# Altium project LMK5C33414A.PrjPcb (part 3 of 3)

## Sheet LMK5C33414A_USB2ANY.SchDoc
size 431 x 279 mm; Date: Not shown in title block; ApprovedBy: Not shown in title block; CheckedBy: Not shown in title block; Author: Not shown in title block; CompanyName: Not shown in title block; Engineer: Not shown in title block; Organization: Not shown in title block; Address1: Not shown in title block; Address2: Not shown in title block; Address3: Not shown in title block; Address4: Not shown in title block; DocumentNumber: 2; Revision: Use project parameter SCH_Rev; SheetNumber: 2; SheetTotal: 3; PageSetup: Record=PageOptions¦CenterHorizontal=True¦CenterVertical=True¦PrintScale=1.00¦XCorrection=1.00¦YCorrection=1.00¦PrintKind=0¦BorderSize=5000000¦LeftOffset=0¦BottomOffset=0¦Orientation=2¦PaperLength=1000¦PaperWidth=1000¦Scale=100¦PaperSource=15¦PrintQuality=600¦MediaType=1¦DitherType=10¦PaperKind=Letter¦PrintScaleMode=1
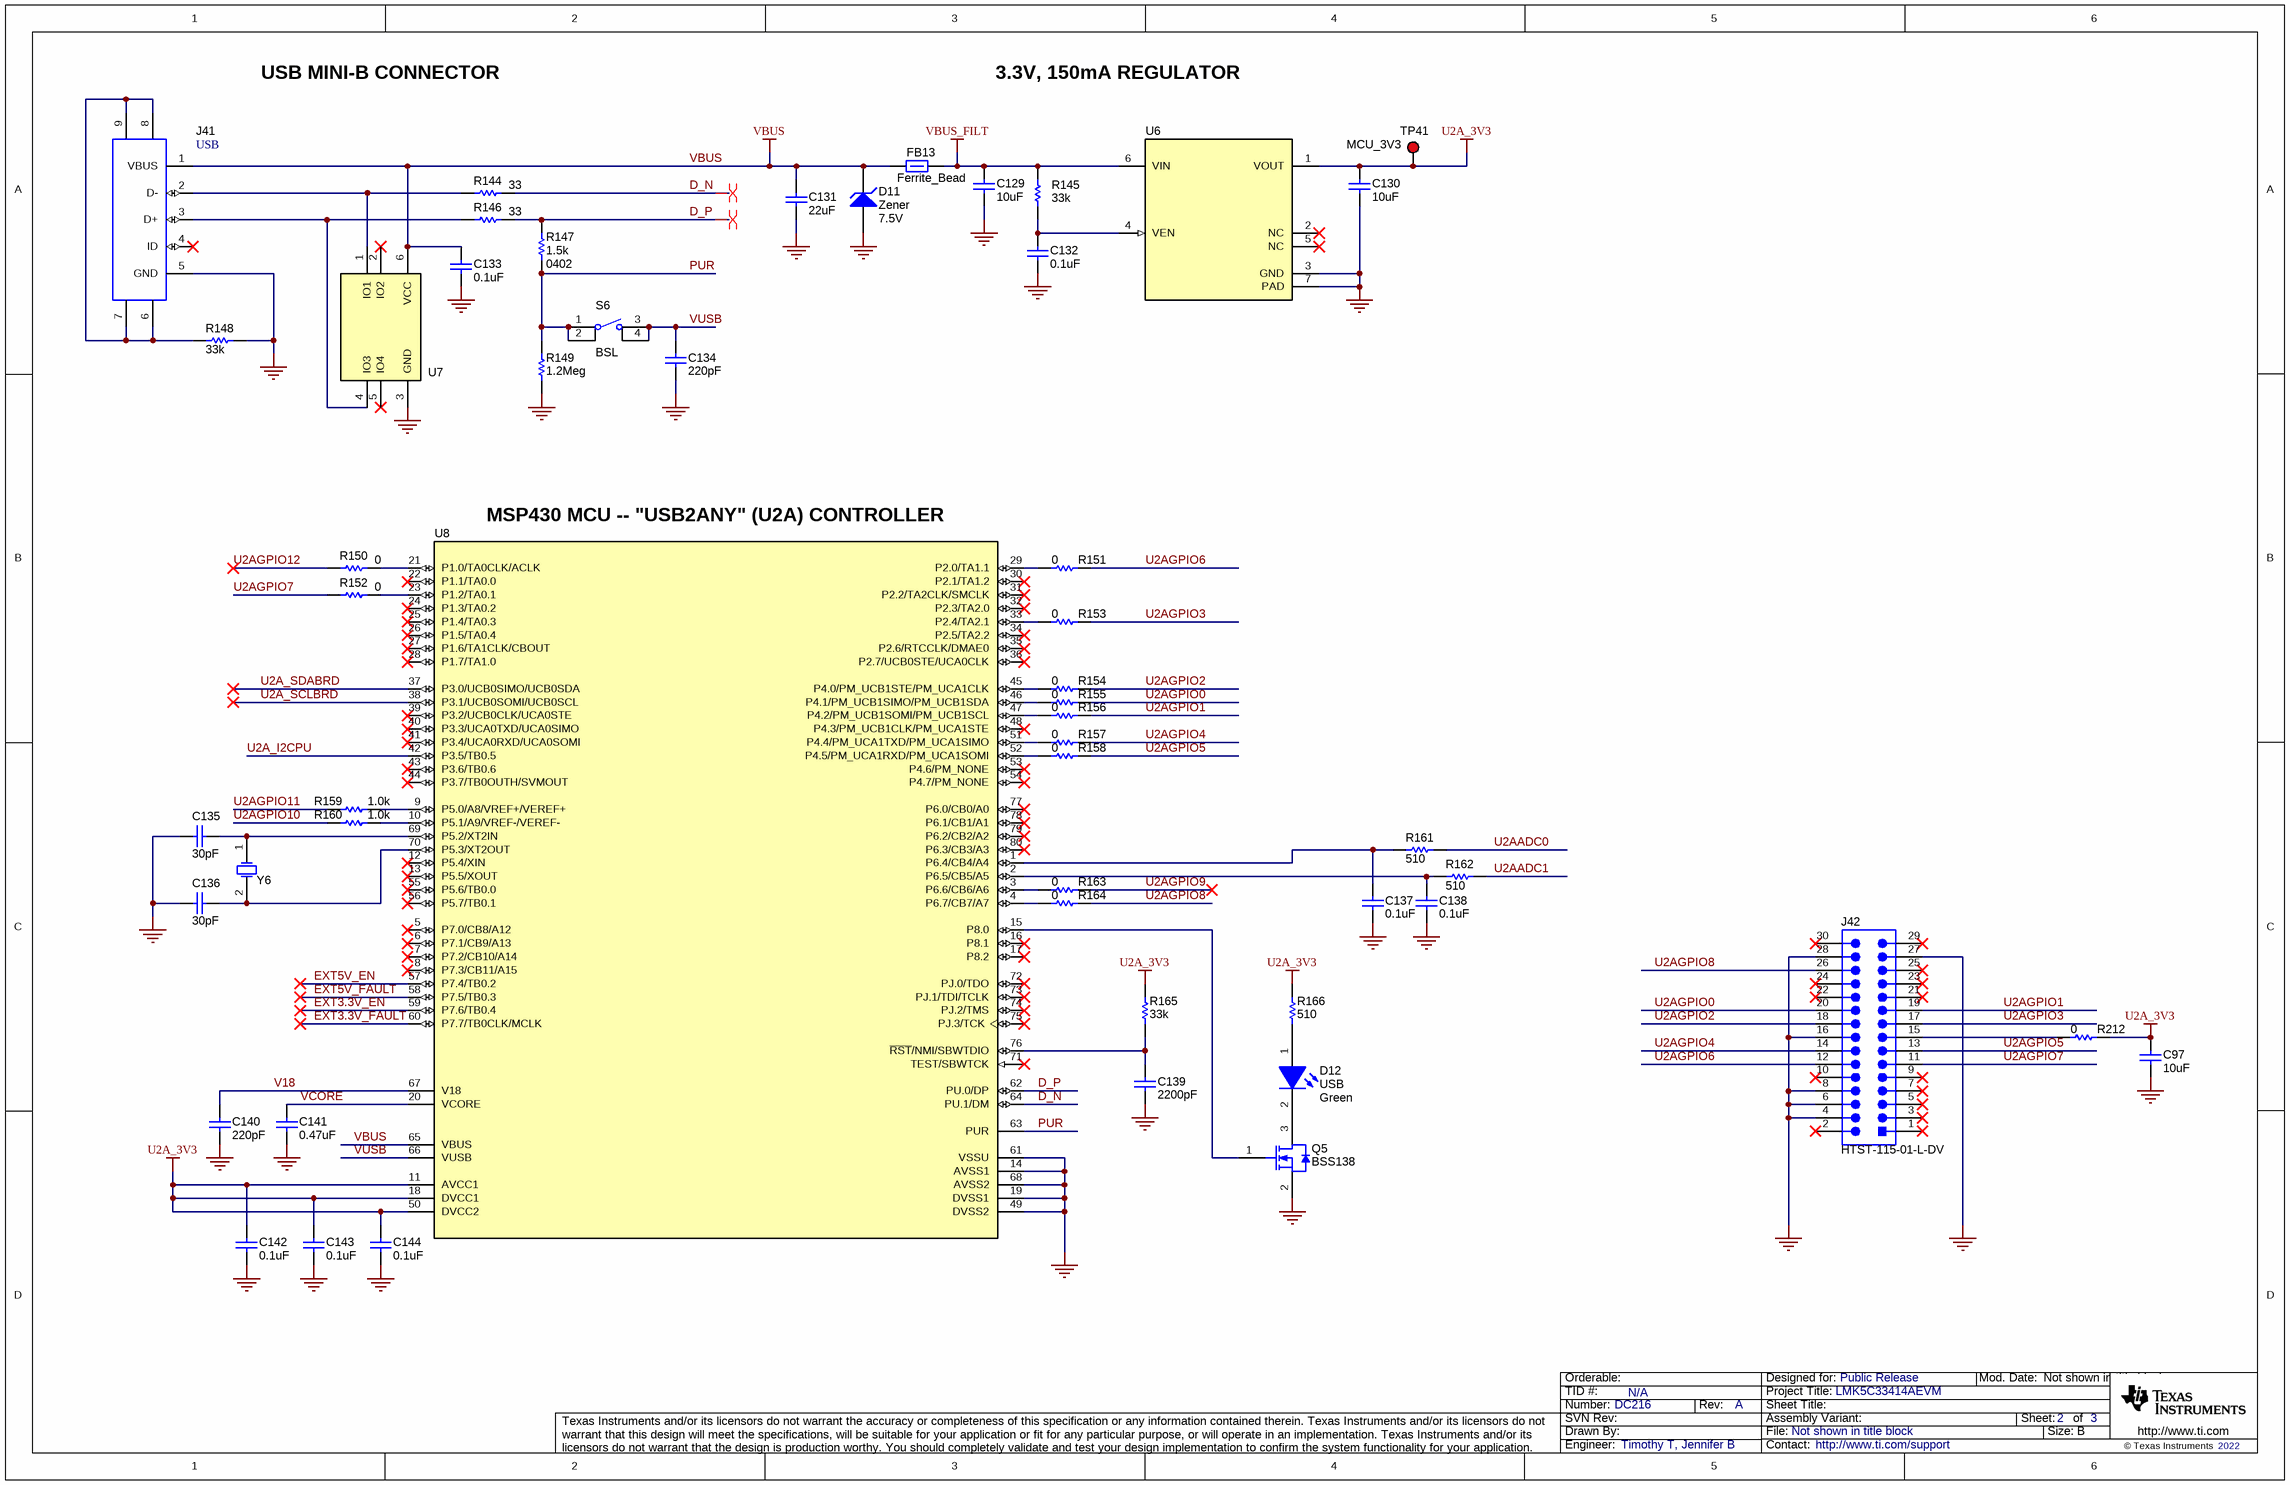
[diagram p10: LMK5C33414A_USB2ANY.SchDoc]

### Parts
C97  ValueDisplayed: 10uF  [0603]  (hidden comment: Capacitor)
C129  ValueDisplayed: 10uF  [0603]  (hidden comment: Capacitor)
C130  ValueDisplayed: 10uF  [0603]  (hidden comment: Capacitor)
C131  ValueDisplayed: 22uF  [0805]  (hidden comment: Capacitor)
C132  ValueDisplayed: 0.1uF  [0603]  (hidden comment: Capacitor)
C133  ValueDisplayed: 0.1uF  [0603]  (hidden comment: Capacitor)
C134  ValueDisplayed: 220pF  [0603]  (hidden comment: Capacitor)
C135  ValueDisplayed: 30pF  [0603]  (hidden comment: Capacitor)
C136  ValueDisplayed: 30pF  [0603]  (hidden comment: Capacitor)
C137  ValueDisplayed: 0.1uF  [0603]  (hidden comment: Capacitor)
C138  ValueDisplayed: 0.1uF  [0603]  (hidden comment: Capacitor)
C139  ValueDisplayed: 2200pF  [0603]  (hidden comment: Capacitor)
C140  ValueDisplayed: 220pF  [0603]  (hidden comment: Capacitor)
C141  ValueDisplayed: 0.47uF  [0603]  (hidden comment: Capacitor)
C142  ValueDisplayed: 0.1uF  [0603]  (hidden comment: Capacitor)
C143  ValueDisplayed: 0.1uF  [0603]  (hidden comment: Capacitor)
C144  ValueDisplayed: 0.1uF  [0603]  (hidden comment: Capacitor)
D11  Zener  value 7.5V  [SMB]
D12  USB  value Green  [LED_LTST-C190]
FB13  Ferrite_Bead  [0603]
J41  USB  [CONN_USB-Mini-B-1734035-2]
J42  HTST-115-01-L-DV  [Samtec_HTST-115-01-x-DV]
Q5  BSS138  [SOT-23]
R144  value 33  [0402]  (hidden comment: Resistor)
R145  value 33k  [0603]  (hidden comment: Resistor)
R146  value 33  [0402]  (hidden comment: Resistor)
R147  value 1.5k  [0402]  (hidden comment: Resistor)
R148  value 33k  [0603]  (hidden comment: Resistor)
R149  value 1.2Meg  [0603]  (hidden comment: Resistor)
R150  value 0  [0603]  (hidden comment: Resistor)
R151  value 0  [0603]  (hidden comment: Resistor)
R152  value 0  [0603]  (hidden comment: Resistor)
R153  value 0  [0603]  (hidden comment: Resistor)
R154  value 0  [0603]  (hidden comment: Resistor)
R155  value 0  [0603]  (hidden comment: Resistor)
R156  value 0  [0603]  (hidden comment: Resistor)
R157  value 0  [0603]  (hidden comment: Resistor)
R158  ValueDisplayed: 0  [0603]  (hidden comment: CRCW06030000Z0EA)
R159  ValueDisplayed: 1.0k  [0603]  (hidden comment: CRCW06031K00JNEA)
R160  ValueDisplayed: 1.0k  [0603]  (hidden comment: CRCW06031K00JNEA)
R161  ValueDisplayed: 510  [0603]  (hidden comment: Resistor)
R162  ValueDisplayed: 510  [0603]  (hidden comment: Resistor)
R163  value 0  [0603]  (hidden comment: Resistor)
R164  value 0  [0603]  (hidden comment: Resistor)
R165  value 33k  [0603]  (hidden comment: Resistor)
R166  ValueDisplayed: 510  [0603]  (hidden comment: Resistor)
R212  value 0  [0603]  (hidden comment: Resistor)
S6  BSL  [SW_FSM4JSMA]
TP41  MCU_3V3  [Keystone5000]
U6  LP5900SD-3.3/NOPB  [NGF0006A]  (value not drawn)
U7  TPD4E004DRYR  [DRY0006A]  (value not drawn)
U8  MSP430F5529IPN  [PN0080A_N]  (value not drawn)
Y6  Xtal  [XTAL_CSM-7X]  (value not drawn)

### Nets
GND: C97.2 C129.1 C130.2 C131.2 C132.1 C133.1 C134.1 C135.2 C136.2 C137.1 C138.1 C139.2 C140.1 C141.1 C142.1 C143.1 C144.1 D11.2(A) J41.5(GND) J42.4 J42.6 J42.8 J42.16 J42.27 J42.28 Q5.2(S) R148.2 R149.1 U6.3(GND) U6.7(PAD) U7.3(GND) U8.14(AVSS1) U8.19(DVSS1) U8.49(DVSS2) U8.61(VSSU) U8.68(AVSS2)
U2A_3V3: C97.1 C130.1 C142.2 C143.2 C144.2 R165.1 R166.2 R212.2 TP41.1 U6.1(VOUT) U8.11(AVCC1) U8.18(DVCC1) U8.50(DVCC2)
VBUS: C131.1 C133.2 D11.1(K) FB13.1 J41.1(VBUS) U7.6(VCC) U8.65(VBUS)
VBUS_FILT: C129.2 FB13.2 R145.1 U6.6(VIN)
D_N: R144.1 U8.64(PU.1/DM)
D_P: R146.1 R147.2 U8.62(PU.0/DP)
EXT3.3V_EN: U8.59(P7.6/TB0.4)
EXT3.3V_FAULT: U8.60(P7.7/TB0CLK/MCLK)
EXT5V_EN: U8.57(P7.4/TB0.2)
EXT5V_FAULT: U8.58(P7.5/TB0.3)
PUR: R147.1 R149.2 S6.1 S6.2 U8.63(PUR)
U2A_I2CPU: U8.42(P3.5/TB0.5)
U2A_SCLBRD: U8.38(P3.1/UCB0SOMI/UCB0SCL)
U2A_SDABRD: U8.37(P3.0/UCB0SIMO/UCB0SDA)
U2AADC0: R161.2
U2AADC1: R162.2
U2AGPIO0: J42.20 R155.1
U2AGPIO1: J42.19 R156.1
U2AGPIO2: J42.18 R154.2
U2AGPIO3: J42.17 R153.2
U2AGPIO4: J42.14 R157.2
U2AGPIO5: J42.13 R158.2
U2AGPIO6: J42.12 R151.2
U2AGPIO7: J42.11 R152.2
U2AGPIO8: J42.26 R164.2
U2AGPIO9: R163.2
U2AGPIO10: R160.2
U2AGPIO11: R159.2
U2AGPIO12: R150.2
V18: C140.2 U8.67(V18)
VCORE: C141.2 U8.20(VCORE)
VUSB: C134.2 S6.3 S6.4 U8.66(VUSB)
NetC132_2: C132.2 R145.2 U6.4(VEN)
NetC135_1: C135.1 U8.69(P5.2/XT2IN) Y6.1(OSC1)
NetC136_1: C136.1 U8.70(P5.3/XT2OUT) Y6.2(OSC2)
NetC137_2: C137.2 R161.1 U8.1(P6.4/CB4/A4)
NetC138_2: C138.2 R162.1 U8.2(P6.5/CB5/A5)
NetC139_1: C139.1 R165.2 U8.76(~{RST}/NMI/SBWTDIO)
NetD12_1: D12.1(A) R166.1
NetD12_2: D12.2(K) Q5.3(D)
NetJ41_2: J41.2(D-) R144.2 U7.1(IO1)
NetJ41_3: J41.3(D+) R146.2 U7.4(IO3)
NetJ41_6: J41.6 J41.7 J41.8 J41.9 R148.1
NetJ42_15: J42.15 R212.1
NetQ5_1: Q5.1(G) U8.15(P8.0)
NetR150_1: R150.1 U8.21(P1.0/TA0CLK/ACLK)
NetR151_1: R151.1 U8.29(P2.0/TA1.1)
NetR152_1: R152.1 U8.23(P1.2/TA0.1)
NetR153_1: R153.1 U8.33(P2.4/TA2.1)
NetR154_1: R154.1 U8.45(P4.0/PM_UCB1STE/PM_UCA1CLK)
NetR155_2: R155.2 U8.46(P4.1/PM_UCB1SIMO/PM_UCB1SDA)
NetR156_2: R156.2 U8.47(P4.2/PM_UCB1SOMI/PM_UCB1SCL)
NetR157_1: R157.1 U8.51(P4.4/PM_UCA1TXD/PM_UCA1SIMO)
NetR158_1: R158.1 U8.52(P4.5/PM_UCA1RXD/PM_UCA1SOMI)
NetR159_1: R159.1 U8.9(P5.0/A8/VREF+/VEREF+)
NetR160_1: R160.1 U8.10(P5.1/A9/VREF-/VEREF-)
NetR163_1: R163.1 U8.3(P6.6/CB6/A6)
NetR164_1: R164.1 U8.4(P6.7/CB7/A7)

Not connected (* = marked no-connect by the designer): J41 4(ID)*; J42 1* 2* 3* 5* 7* 9* 10* 21* 22* 23* 24* 25* 29* 30*; U6 2(NC)* 5(NC)*; U7 2(IO2)* 5(IO4)*; U8 5(P7.0/CB8/A12)* 6(P7.1/CB9/A13)* 7(P7.2/CB10/A14)* 8(P7.3/CB11/A15)* 12(P5.4/XIN)* 13(P5.5/XOUT)* 16(P8.1)* 17(P8.2)* 22(P1.1/TA0.0)* 24(P1.3/TA0.2)* 25(P1.4/TA0.3)* 26(P1.5/TA0.4)* 27(P1.6/TA1CLK/CBOUT)* 28(P1.7/TA1.0)* 30(P2.1/TA1.2)* 31(P2.2/TA2CLK/SMCLK)* 32(P2.3/TA2.0)* 34(P2.5/TA2.2)* 35(P2.6/RTCCLK/DMAE0)* 36(P2.7/UCB0STE/UCA0CLK)* 39(P3.2/UCB0CLK/UCA0STE)* 40(P3.3/UCA0TXD/UCA0SIMO)* 41(P3.4/UCA0RXD/UCA0SOMI)* 43(P3.6/TB0.6)* 44(P3.7/TB0OUTH/SVMOUT)* 48(P4.3/PM_UCB1CLK/PM_UCA1STE)* 53(P4.6/PM_NONE)* 54(P4.7/PM_NONE)* 55(P5.6/TB0.0)* 56(P5.7/TB0.1)* 71(TEST/SBWTCK)* 72(PJ.0/TDO)* 73(PJ.1/TDI/TCLK)* 74(PJ.2/TMS)* 75(PJ.3/TCK)* 77(P6.0/CB0/A0)* 78(P6.1/CB1/A1)* 79(P6.2/CB2/A2)* 80(P6.3/CB3/A3)*

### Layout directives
differential pair: D_N, D_P

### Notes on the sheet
- USB MINI-B CONNECTOR
- 3.3V, 150mA REGULATOR
- (near U8) MSP430 MCU -- "USB2ANY" (U2A) CONTROLLER

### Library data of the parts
C97 C130 = CMP-0007003-5: CAP, CERM, 10 uF, 10 V, +/- 20%, X5R, 0603; PartNumber: C1608X5R1A106M080AC; Manufacturer: TDK; Polarized: N; Value: 10uF; U/M: EA; Cap_F: 10µF; ESR_ohm: 7.8m; Value1: 0.0078 ohm; VDC_V: 10V; IRMS_A: 1.85A; TaMin_C: -55°C; TaMax_C: 85°C; SizeArea_mm2: 1.28; SizeAreaWB_mm2: 4.68; SizeX_mm: 1.6; SizeY_mm: 0.8; SizeZ_mm: 1; AEC Category: Q200
C129 = CMP-0007003-5: CAP, CERM, 10 uF, 10 V, +/- 20%, X5R, 0603; Manufacturer: TDK; PartNumber: C1608X5R1A106M080AC; ESR_ohm: 7.8m; IRMS_A: 1.85A; Polarized: N; TaMax_C: 85°C; TaMin_C: -55°C; VDC_V: 10V; Cap_F: 10µF; Value: 10uF; Value1: 0.0078 ohm; U/M: EA; SizeArea_mm2: 1.28; SizeAreaWB_mm2: 4.68; SizeX_mm: 1.6; SizeY_mm: 0.8; SizeZ_mm: 1; AEC Category: Q200
C131 = CMP-0008403-2: CAP, CERM, 22 uF, 10 V, +/- 20%, X5R, 0805; PartNumber: LMK212BJ226MG-T; Manufacturer: Taiyo Yuden; Polarized: N; Value: 22uF; U/M: EA; Cap_F: 22µF; Value1: Unknown; VDC_V: 10V; TaMin_C: -55°C; TaMax_C: 85°C; AEC Category: Q200; SizeArea_mm2: 2.5; SizeAreaWB_mm2: 6.75; SizeX_mm: 2; SizeY_mm: 1.25; SizeZ_mm: 1.45
C132 C133 C137 C138 C142-C144 = CMP-0006857-4: CAP, CERM, 0.1 uF, 16 V, +/- 5%, X7R, 0603; PartNumber: C0603C104J4RACTU; Manufacturer: Kemet; Polarized: N; Value: 0.1uF; U/M: EA; Cap_F: 100nF; Value1: Unknown; VDC_V: 16V; TaMin_C: -55°C; TaMax_C: 125°C; AEC Category: Q200; SizeArea_mm2: 1.28; SizeAreaWB_mm2: 4.68; SizeX_mm: 1.6; SizeY_mm: 0.8; SizeZ_mm: 1
C134 C140 = CMP-0006776-4: CAP, CERM, 220 pF, 50 V, +/- 1%, C0G/NP0, 0603; PartNumber: 06035A221FAT2A; Manufacturer: AVX; Polarized: N; Value: 220pF; U/M: EA; ESR_ohm: 0.083; Value1: 0.083 ohm; VDC_V: 50V; TaMin_C: -55°C; TaMax_C: 125°C; AEC Category: Q200; SizeArea_mm2: 1.28; SizeAreaWB_mm2: 4.68; SizeX_mm: 1.6; SizeY_mm: 0.8; SizeZ_mm: 1
C135 C136 = CMP-0007261-4: CAP, CERM, 30 pF, 100 V, +/- 5%, C0G/NP0, 0603; PartNumber: GRM1885C2A300JA01D; Manufacturer: MuRata; Polarized: N; Value: 30pF; U/M: EA; Value1: Unknown; VDC_V: 100V; TaMin_C: -55°C; TaMax_C: 125°C; AEC Category: Q200; SizeArea_mm2: 1.28; SizeAreaWB_mm2: 4.68; SizeX_mm: 1.6; SizeY_mm: 0.8; SizeZ_mm: 1
C139 = CMP-0006898-4: CAP, CERM, 2200 pF, 50 V, +/- 10%, X7R, 0603; PartNumber: C0603C222K5RACTU; Manufacturer: Kemet; Polarized: N; Value: 2200pF; U/M: EA; Cap_F: 2.2nF; Value1: Unknown; VDC_V: 50V; TaMin_C: -55°C; TaMax_C: 125°C; AEC Category: Q200; SizeArea_mm2: 1.28; SizeAreaWB_mm2: 4.68; SizeX_mm: 1.6; SizeY_mm: 0.8; SizeZ_mm: 1
C141 = CMP-0007373-4: CAP, CERM, 0.47 uF, 10 V, +/- 10%, X7R, 0603; PartNumber: GRM188R71A474KA61D; Manufacturer: MuRata; Polarized: N; Value: 0.47uF; U/M: EA; Cap_F: 470nF; Value1: Unknown; VDC_V: 10V; TaMin_C: -55°C; TaMax_C: 125°C; AEC Category: Q200; SizeArea_mm2: 1.28; SizeAreaWB_mm2: 4.68; SizeX_mm: 1.6; SizeY_mm: 0.8; SizeZ_mm: 1
D11 = CMP-0005670-2: Diode, Zener, 7.5 V, 550 mW, SMB; PartNumber: 1SMB5922BT3G; Manufacturer: ON Semiconductor; Power_W: 550mW; Value1: 0.55W; RJA_CperW: 226; AEC Category: Q101; SizeArea_mm2: 21.336; SizeAreaWB_mm2: 44.156; SizeX_mm: 5.6; SizeY_mm: 3.81; SizeZ_mm: 2.6
D12 = CMP-0002827-2: LED, Green, SMD; Manufacturer: Lite-On; PartNumber: LTST-C190GKT; Vf_V: 2.1V; Io_A: 20mA; Power_TotalModule: 100mW; Value1: 0.1W; U/M: EA
FB13 = CMP-0003426-2: Ferrite Bead, 60 ohm @ 100 MHz, 3.5 A, 0603; PartNumber: MPZ1608S600ATAH0; Manufacturer: TDK; Value: 60 ohm; Imax_A: 3.5A; DCR_ohm: 0.02; Value1: 0.02 ohm; ZTyp@100MHz_Ohm: 60; SizeAreaWB_mm2: 4.68; SizeArea_mm2: 1.28; SizeX_mm: 1.6; SizeY_mm: 0.8; SizeZ_mm: 1
J41 = CMP-0054920-1: Connector, Receptacle, Mini-USB Type B, R/A, Top Mount SMT; PartNumber: 1734035-2; Manufacturer: TE Connectivity; CNHeader: FALSE; CT: TRUE; Gender: Female; Green_Lifecycle: Active; Green_REACh: Passed
J42 = CMP-0077170-1: Header, 2.54mm, 15x2, Gold, SMD; Manufacturer: Samtec; CNHeader: False; Shrouded: Y; Gender: Male; Row_Count: 2; RowSpacing_mm: 2.54
Q5 = CMP-0000755-1: MOSFET, N-CH, 50 V, 0.22 A, SOT-23; Manufacturer: Fairchild Semiconductor; Alternate Manufacturer: None; U/M: EA; ChType: N; Value: 50V; Rdson45_ohm: 6; Value2: 1.7 nC; QgTyp_nC: 1.7; Vgs_V: 20V; IdsMax_A: 2.2dA; AEC Category: Q101; SizeArea_mm2: 7.5; SizeAreaWB_mm2: 14; SizeX_mm: 2.5; SizeY_mm: 3; SizeZ_mm: 1.1
R144 R146 = CMP-0026908-3: RES, 33, 5%, 0.063 W, AEC-Q200 Grade 0, 0402; PartNumber: CRCW040233R0JNED; Manufacturer: Vishay-Dale; Value_Code: 33R0; Power_W: 63mW; Value2: 0.063W; VDC_V: 50V; TempCo: 200 ppm/C; EIA_Code: E24; AEC Category: Q200; AEC Grade: 0; AEC Qualified: Y; SizeArea_mm2: 0.5; SizeX_mm: 1; SizeZ_mm: 0.6
R145 R148 R165 = CMP-0025786-4: RES, 33 k, 5%, 0.1 W, AEC-Q200 Grade 0, 0603; PartNumber: CRCW060333K0JNEA; Manufacturer: Vishay-Dale; Value_Code: 33k0; Power_W: 100mW; Value2: 0.1W; VDC_V: 75V; TempCo: 200 ppm/C; EIA_Code: E24; AEC Category: Q200; AEC Grade: 0; AEC Qualified: Y; SizeArea_mm2: 1.28; SizeX_mm: 1.6; SizeY_mm: 0.8; SizeZ_mm: 1
R147 = CMP-0026856-5: RES, 1.5 k, 5%, 0.063 W, AEC-Q200 Grade 0, 0402; PartNumber: CRCW04021K50JNED; Manufacturer: Vishay-Dale; Value_Code: 1k50; Power_W: 63mW; Value2: 0.063W; VDC_V: 50V; TempCo: 200 ppm/C; EIA_Code: E24; AEC Category: Q200; AEC Grade: 0; AEC Qualified: Y; SizeArea_mm2: 0.5; SizeX_mm: 1; SizeZ_mm: 0.6
R149 = CMP-0025738-4: RES, 1.2 M, 5%, 0.1 W, AEC-Q200 Grade 0, 0603; PartNumber: CRCW06031M20JNEA; Manufacturer: Vishay-Dale; Res_ohm: 1.2M; Value_Code: 1M20; Power_W: 100mW; Value2: 0.1W; VDC_V: 75V; TempCo: 200 ppm/C; EIA_Code: E24; AEC Category: Q200; AEC Grade: 0; AEC Qualified: Y; SizeArea_mm2: 1.28; SizeX_mm: 1.6; SizeY_mm: 0.8; SizeZ_mm: 1
R150-R157 R163 R164 R212 = CMP-0025697-4: RES, 0, 5%, 0.1 W, AEC-Q200 Grade 0, 0603; PartNumber: CRCW06030000Z0EA; Manufacturer: Vishay-Dale; Value_Code: 0000; Power_W: 100mW; Value2: 0.1W; VDC_V: 75V; TempCo: 200 ppm/C; EIA_Code: E24; AEC Category: Q200; AEC Qualified: Y; SizeArea_mm2: 1.28; SizeX_mm: 1.6; SizeY_mm: 0.8; SizeZ_mm: 1
R158 = CMP-0025697-4: RES, 0, 5%, 0.1 W, AEC-Q200 Grade 0, 0603; Manufacturer: Vishay-Dale; Value: 0; Value_Code: 0000; Power_W: 100mW; Value2: 0.1W; VDC_V: 75V; TempCo: 200 ppm/C; EIA_Code: E24; SizeX_mm: 1.6; SizeY_mm: 0.8; SizeZ_mm: 1; SizeArea_mm2: 1.28; AEC Qualified: Y; AEC Category: Q200
R159 R160 = CMP-0025729-4: RES, 1.0 k, 5%, 0.1 W, AEC-Q200 Grade 0, 0603; Manufacturer: Vishay-Dale; Value: 1.0k; Res_ohm: 1k; Value_Code: 1k00; Power_W: 100mW; Value2: 0.1W; VDC_V: 75V; TempCo: 200 ppm/C; EIA_Code: E24; SizeX_mm: 1.6; SizeY_mm: 0.8; SizeZ_mm: 1; SizeArea_mm2: 1.28; AEC Qualified: Y; AEC Category: Q200; AEC Grade: 0
R161 R162 R166 = CMP-0025823-4: RES, 510, 5%, 0.1 W, AEC-Q200 Grade 0, 0603; PartNumber: CRCW0603510RJNEA; Manufacturer: Vishay-Dale; Value: 510; Value_Code: 510R; Power_W: 100mW; Value2: 0.1W; VDC_V: 75V; TempCo: 200 ppm/C; EIA_Code: E24; AEC Category: Q200; AEC Grade: 0; AEC Qualified: Y; SizeArea_mm2: 1.28; SizeX_mm: 1.6; SizeY_mm: 0.8; SizeZ_mm: 1
S6 = CMP-0002134-3: Switch, Tactile, SPST-NO, 0.05A, 12V, SMT; PartNumber: FSM4JSMA; Manufacturer: TE Connectivity; CurrentRating_mA: 50A; PositionCount: 1; SwitchFunction: Off-Mom
TP41 = CMP-0055137-1: Test Point, Miniature, Red, TH; Manufacturer: Keystone; CNHeader: FALSE; ContactFinish: Silver; CT: TRUE; Green_Lifecycle: Active; Green_REACh: Passed
U6 = CMP-0066010-1: 150-mA Ultra-Low Noise LDO for RF and Analog Circuits Requires No Bypass Capacitor, NGF0006A (WSON-6); Manufacturer: Texas Instruments; CompType: IC; Green_Lifecycle: Active; Green_REACh: Passed; SizeArea_mm2: 5.5; SizeAreaWB_mm2: 11.2; SizeX_mm: 2.5; SizeY_mm: 2.2; SizeZ_mm: 0.8; U/M: EA
U7 = CMP-0043115-3: 4-Channel ESD Protection Array for High-Speed Data Interfaces, DRY0006A (USON-6); Manufacturer: Texas Instruments; 1394 / Firewire: TRUE; Breakdown Voltage(Min)(V): 6; Eco-Plan: Green (RoHS & no Sb/Br); IEC 61000-4-2 Air-Gap(+/- kV): 12; IEC 61000-4-2 Contact(+/- kV): 8; IO Capacitance(Typ)(pF): 1.6; IO Leakage Current(nA): 1; AEC Category: Q200; AEC Qualified: N; CompType: IC; Rating: Catalog; SizeArea_mm2: 1.45; SizeAreaWB_mm2: 4.9; SizeX_mm: 1.0; SizeZ_mm: 0.6
U8 = CMP-0038965-1: 25 MHz Mixed Signal Microcontroller with 128 KB Flash, 8192 B SRAM and 63 GPIOs, -40 to 85 degC, 80-pin QFP (PN), Green (RoHS & no Sb/Br); Manufacturer: Texas Instruments; ADC: 12-bit SAR; ADC Channels: 16; Brown Out Reset: Yes; DMA: 3; Flash(KB): 128; Frequency(MHz): 25; GPIO: 63; Multiplier: 32x32; SRAM(B): 8192; SubFamily: 5 Series; Timers - 16-bit: 4; USB: 1; USCI_A (UART/LIN/IrDA/SPI): 2
Y6 = CMP-0004572-3: Crystal, 24.000 MHz, 20pF, SMD; PartNumber: ECS-240-20-5PX-TR; Manufacturer: ECS Inc.; TaMin_C: -10°C; TaMax_C: 70°C; Frequency Stability: +/-50ppm; Frequency_Fixed: 24MHz

## Sheet LMK5C33414A_Hardware.SchDoc
size 431 x 279 mm; Date: Not shown in title block; ApprovedBy: Not shown in title block; CheckedBy: Not shown in title block; Author: Not shown in title block; CompanyName: Not shown in title block; Engineer: Not shown in title block; Organization: Not shown in title block; Address1: Not shown in title block; Address2: Not shown in title block; Address3: Not shown in title block; Address4: Not shown in title block; DocumentNumber: 3; Revision: Use project parameter SCH_Rev; SheetNumber: 3; SheetTotal: 3; PageSetup: Record=PageOptions¦CenterHorizontal=True¦CenterVertical=True¦PrintScale=1.00¦XCorrection=1.00¦YCorrection=1.00¦PrintKind=0¦BorderSize=5000000¦LeftOffset=0¦BottomOffset=0¦Orientation=2¦PaperLength=1000¦PaperWidth=1000¦Scale=100¦PaperSource=15¦PrintQuality=600¦MediaType=1¦DitherType=10¦PaperKind=Letter¦PrintScaleMode=1
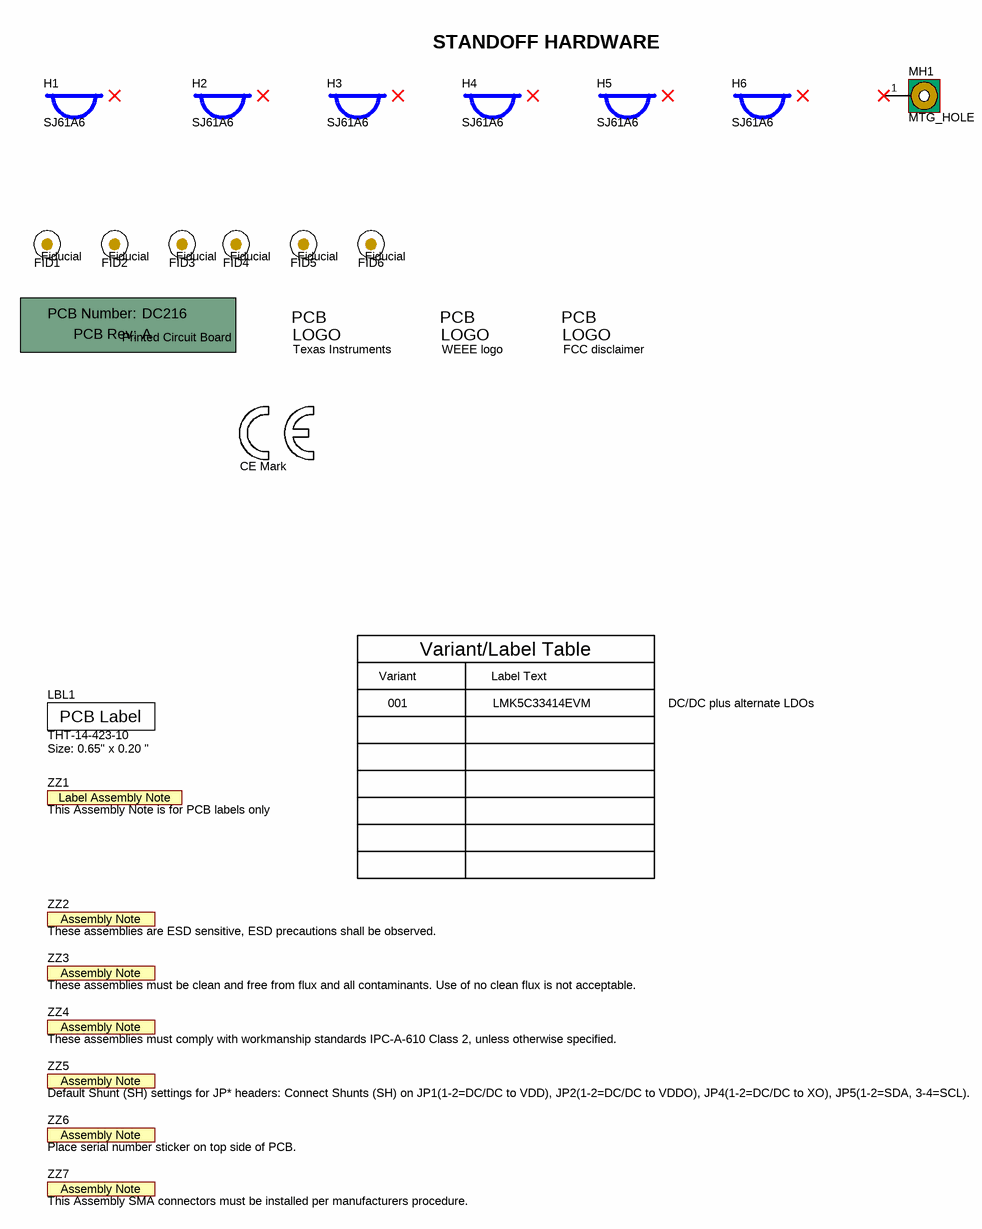
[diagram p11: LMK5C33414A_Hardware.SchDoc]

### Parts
!PCB1  Printed Circuit Board  (mechanical)
FID1  Fiducial  [Fiducial10-20]
FID2  Fiducial  [Fiducial10-20]
FID3  Fiducial  [Fiducial10-20]
FID4  Fiducial  [Fiducial10-20]
FID5  Fiducial  [Fiducial10-20]
FID6  Fiducial  [Fiducial10-20]
H1  SJ61A6  [3M_SJ61A6]
H2  SJ61A6  [3M_SJ61A6]
H3  SJ61A6  [3M_SJ61A6]
H4  SJ61A6  [3M_SJ61A6]
H5  SJ61A6  [3M_SJ61A6]
H6  SJ61A6  [3M_SJ61A6]
LBL1  THT-14-423-10  Note: Size: 0.65" x 0.20 "  [Label_650x200]
Logo1  Texas Instruments  [TI_Stacked_Overlay_Medium]  (no BOM)
Logo2  FCC disclaimer  [FCC_disclaimer]  (no BOM)
Logo3  CE Mark  [CE_Mark_5mm]  (no BOM)
Logo4  WEEE logo  [WEEE_Minimum]  (no BOM)
MH1  MTG_HOLE  [MTGP_252mil_157mil_6Via]  (no BOM)
ZZ1  This Assembly Note is for PCB labels only  [AssemblyNoteLabel]  (no BOM)
ZZ2  These assemblies are ESD sensitive, ESD precautions shall be observed.  [AssemblyNote]  (no BOM)
ZZ3  These assemblies must be clean and free from flux and all contaminants. Use of no clean flux is not acceptable.  [AssemblyNote]  (no BOM)
ZZ4  These assemblies must comply with workmanship standards IPC-A-610 Class 2, unless otherwise specified.  [AssemblyNote]  (no BOM)
ZZ5  Default Shunt (SH) settings for JP* headers: Connect Shunts (SH) on JP1(1-2=DC/DC to VDD), JP2(1-2=DC/DC to VDDO), JP4(1-2=DC/DC to XO), JP5(1-2=SDA, 3-4=SCL).  [AssemblyNote]  (no BOM)
ZZ6  Place serial number sticker on top side of PCB.  [AssemblyNote]  (no BOM)
ZZ7  This Assembly SMA connectors must be installed per manufacturers procedure.  [AssemblyNote]  (no BOM)

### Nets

Not connected (* = marked no-connect by the designer): MH1 1*

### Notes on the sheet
- STANDOFF HARDWARE
- Variant
- Variant/Label Table
- Label Text
- 001
- LMK5C33414EVM
- DC/DC plus alternate LDOs

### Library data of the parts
!PCB1 = CMP-0003618-2: Manufacturer: Any; PartNumber: DC216
FID1-FID6 = CMP-0077181-1: Fiducial mark.  There is nothing to buy or mount.
H1-H6 = CMP-0079645-1: BUMPER CYLIN 0.312" DIA; Manufacturer: 3M; Green_Lifecycle: Not Set; Green_REACh: Incomplete
LBL1 = CMP-0003625-1: Thermal Transfer Printable Labels, 0.650" W x 0.200" H - 10,000 per roll; Manufacturer: Brady
Logo1 = CMP-0074838-1: Texas Instrument Corporate Signature; SymbolCreator: a0412235; Lib Reference: TI_Logo
Logo2 = CMP-0074847-1: FCC_disclaimer
Logo3 = CMP-0074844-1: SymbolCreator: a0412235
Logo4 = CMP-0074769-1
MH1 = CMP-0078422-2: PCB Mounting Hole; Manufacturer: Any; Key: Mounting Hole (non-standard)
ZZ1 = CMP-0003616-3
ZZ2 = CMP-0077236-1
ZZ3 = CMP-0077237-1
ZZ4 = CMP-0077238-1
ZZ5-ZZ7 = CMP-0003615-1: This Assembly Note will show in the PcbDoc and associated outputs

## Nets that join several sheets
GND: LMK5C33414A_Power (44 pins), LMK5C33414A_Power_Alternate (16 pins), LMK5C33414A_PowerDist (44 pins), LMK5C33414A_XO (17 pins), LMK5C33414A_Inputs (40 pins), LMK5C33414A_DUT (21 pins), LMK5C33414A_Logic (26 pins), LMK5C33414A_Outputs_A (48 pins), LMK5C33414A_Outputs_B (72 pins), LMK5C33414A_Outputs_C (48 pins), LMK5C33414A_USB2ANY (36 pins)
LDO3_IN: LMK5C33414A_Power (10 pins), LMK5C33414A_Power_Alternate (10 pins)
U2A_3V3: LMK5C33414A_Logic (R57.2 R58.2 R59.2 R60.2), LMK5C33414A_USB2ANY (13 pins)
VCC_XO: LMK5C33414A_Power (JP4.2 JP4.4 JP4.6 JP4.8), LMK5C33414A_PowerDist (R15.1), LMK5C33414A_XO (C78.1 FB12.2)
VDD_PLANE: LMK5C33414A_Power (5 pins), LMK5C33414A_PowerDist (9 pins), LMK5C33414A_Logic (R54.2)
VDDGPIO: LMK5C33414A_PowerDist (NT1.1), LMK5C33414A_Logic (10 pins)
VDDO_PLANE: LMK5C33414A_Power (5 pins), LMK5C33414A_PowerDist (5 pins)
IN0_N: LMK5C33414A_Inputs (R31.2), LMK5C33414A_DUT (U1.35)
IN0_P: LMK5C33414A_Inputs (R27.2), LMK5C33414A_DUT (U1.34)
IN1_N: LMK5C33414A_Inputs (R38.2), LMK5C33414A_DUT (U1.38)
IN1_P: LMK5C33414A_Inputs (R34.2), LMK5C33414A_DUT (U1.39)
IN2_N: LMK5C33414A_Inputs (R130.1), LMK5C33414A_DUT (U1.43)
IN2_P: LMK5C33414A_Inputs (R126.1), LMK5C33414A_DUT (U1.42)
IN3_N: LMK5C33414A_Inputs (R142.2 R143.1 R193.1), LMK5C33414A_DUT (U1.45)
IN3_P: LMK5C33414A_Inputs (R138.1 R139.2 R193.2), LMK5C33414A_DUT (U1.46)
LDO1: LMK5C33414A_Power (JP1.3), LMK5C33414A_Power_Alternate (C2.1 U10.10 U10.11 U10.12)
LDO2: LMK5C33414A_Power (JP2.3), LMK5C33414A_Power_Alternate (C9.1 U11.10 U11.11 U11.12)
LMKGPIO0: LMK5C33414A_DUT (U1.50), LMK5C33414A_Logic (6 pins)
LMKGPIO1: LMK5C33414A_DUT (U1.64), LMK5C33414A_Logic (6 pins)
LMKGPIO2: LMK5C33414A_DUT (U1.10), LMK5C33414A_Logic (6 pins)
LMKPDN: LMK5C33414A_DUT (U1.36), LMK5C33414A_Logic (5 pins)
LMKSCK: LMK5C33414A_DUT (U1.17), LMK5C33414A_Logic (6 pins)
LMKSCS_ADD: LMK5C33414A_DUT (U1.18), LMK5C33414A_Logic (5 pins)
LMKSDIO: LMK5C33414A_DUT (U1.16), LMK5C33414A_Logic (5 pins)
OUT0_N: LMK5C33414A_DUT (U1.3), LMK5C33414A_Outputs_A (R10.1)
OUT0_P: LMK5C33414A_DUT (U1.2), LMK5C33414A_Outputs_A (R6.1)
OUT1_N: LMK5C33414A_DUT (U1.4), LMK5C33414A_Outputs_A (R80.1)
OUT1_P: LMK5C33414A_DUT (U1.5), LMK5C33414A_Outputs_A (R7.1)
OUT2_N: LMK5C33414A_DUT (U1.13), LMK5C33414A_Outputs_A (R84.1)
OUT2_P: LMK5C33414A_DUT (U1.12), LMK5C33414A_Outputs_A (R81.1)
OUT3_N: LMK5C33414A_DUT (U1.14), LMK5C33414A_Outputs_A (R87.1)
OUT3_P: LMK5C33414A_DUT (U1.15), LMK5C33414A_Outputs_A (R83.1)
OUT4_N: LMK5C33414A_DUT (U1.26), LMK5C33414A_Outputs_B (R93.1)
OUT4_P: LMK5C33414A_DUT (U1.27), LMK5C33414A_Outputs_B (R89.1)
OUT5_N: LMK5C33414A_DUT (U1.25), LMK5C33414A_Outputs_B (R95.1)
OUT5_P: LMK5C33414A_DUT (U1.24), LMK5C33414A_Outputs_B (R91.1)
OUT6_N: LMK5C33414A_DUT (U1.30), LMK5C33414A_Outputs_B (R100.1)
OUT6_P: LMK5C33414A_DUT (U1.29), LMK5C33414A_Outputs_B (R97.1)
OUT7_N: LMK5C33414A_DUT (U1.31), LMK5C33414A_Outputs_B (R102.1)
OUT7_P: LMK5C33414A_DUT (U1.32), LMK5C33414A_Outputs_B (R98.1)
OUT8_N: LMK5C33414A_DUT (U1.52), LMK5C33414A_Outputs_B (R107.1)
OUT8_P: LMK5C33414A_DUT (U1.51), LMK5C33414A_Outputs_B (R104.1)
OUT9_N: LMK5C33414A_DUT (U1.53), LMK5C33414A_Outputs_B (R108.1)
OUT9_P: LMK5C33414A_DUT (U1.54), LMK5C33414A_Outputs_B (R106.1)
OUT10_N: LMK5C33414A_DUT (U1.57), LMK5C33414A_Outputs_C (R114.1)
OUT10_P: LMK5C33414A_DUT (U1.56), LMK5C33414A_Outputs_C (R110.1)
OUT11_N: LMK5C33414A_DUT (U1.58), LMK5C33414A_Outputs_C (R116.1)
OUT11_P: LMK5C33414A_DUT (U1.59), LMK5C33414A_Outputs_C (R112.1)
OUT12_N: LMK5C33414A_DUT (U1.61), LMK5C33414A_Outputs_C (R123.1)
OUT12_P: LMK5C33414A_DUT (U1.60), LMK5C33414A_Outputs_C (R118.1)
OUT13_N: LMK5C33414A_DUT (U1.62), LMK5C33414A_Outputs_C (R124.1)
OUT13_P: LMK5C33414A_DUT (U1.63), LMK5C33414A_Outputs_C (R120.1)
U2A_I2CPU: LMK5C33414A_Logic (U5.2), LMK5C33414A_USB2ANY (U8.42)
U2AGPIO0: LMK5C33414A_Logic (JP5.A01 R57.1), LMK5C33414A_USB2ANY (J42.20 R155.1)
U2AGPIO1: LMK5C33414A_Logic (JP5.A02 R58.1), LMK5C33414A_USB2ANY (J42.19 R156.1)
U2AGPIO2: LMK5C33414A_Logic (JP5.A04), LMK5C33414A_USB2ANY (J42.18 R154.2)
U2AGPIO3: LMK5C33414A_Logic (R76.1), LMK5C33414A_USB2ANY (J42.17 R153.2)
U2AGPIO4: LMK5C33414A_Logic (JP5.A05), LMK5C33414A_USB2ANY (J42.14 R157.2)
U2AGPIO5: LMK5C33414A_Logic (JP5.A06), LMK5C33414A_USB2ANY (J42.13 R158.2)
U2AGPIO6: LMK5C33414A_Logic (JP5.A07), LMK5C33414A_USB2ANY (J42.12 R151.2)
U2AGPIO7: LMK5C33414A_Logic (R52.1), LMK5C33414A_USB2ANY (J42.11 R152.2)
U2AGPIO8: LMK5C33414A_Logic (R64.1), LMK5C33414A_USB2ANY (J42.26 R164.2)
VDD_APLL1_XO: LMK5C33414A_PowerDist (C47.1 C48.2 FB7.2 TP14.1), LMK5C33414A_DUT (U1.8)
VDD_APLL2: LMK5C33414A_PowerDist (C53.1 C54.2 FB9.2 TP16.1), LMK5C33414A_DUT (U1.23)
VDD_APLL3: LMK5C33414A_PowerDist (C59.1 C60.2 FB11.2 TP18.1), LMK5C33414A_DUT (U1.47)
VDD_DIG: LMK5C33414A_PowerDist (C41.1 C42.2 FB5.2 TP12.1), LMK5C33414A_DUT (U1.41)
VDD_IN0: LMK5C33414A_PowerDist (C29.1 C30.2 FB1.2 TP8.1), LMK5C33414A_DUT (U1.33)
VDD_IN1: LMK5C33414A_PowerDist (C35.1 C36.2 FB3.2 TP10.1), LMK5C33414A_DUT (U1.37)
VDD_IN23: LMK5C33414A_PowerDist (C56.1 C57.2 FB10.2 TP17.1), LMK5C33414A_DUT (U1.44)
VDDO_0_1: LMK5C33414A_PowerDist (C32.1 C33.2 FB2.2 TP9.1), LMK5C33414A_DUT (U1.1)
VDDO_2_3: LMK5C33414A_PowerDist (C38.1 C39.2 FB4.2 TP11.1), LMK5C33414A_DUT (U1.11)
VDDO_4_TO_7: LMK5C33414A_PowerDist (C44.1 C45.2 FB6.2 TP13.1), LMK5C33414A_DUT (U1.28)
VDDO_8_TO_13: LMK5C33414A_PowerDist (C50.1 C51.2 FB8.2 TP15.1), LMK5C33414A_DUT (U1.55)
XO3: LMK5C33414A_XO (6 pins), LMK5C33414A_DUT (C71.2)

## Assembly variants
001: not fitted C29 C35 C68 C69 C73 C74 C76 C77 C81 C83 C83 C84 C85 C86 C87 C88 C91 C92 C93 C94 C95 D11 J2 J3 J5 J5 J5 J5 R28 R28 R28 R29 R29 R29 R29 R30 R31 R32 R32 R35 R35 R35 R36 R36 R36 R38 R39 R39 R39 R42 R45 R46 R46 R46 R47 R48 R49 R50 R59 R60 R75 R78 R78 R79 R79 R82 R82 R85 R85 R86 R86 R88 R88 R90 R90 R92 R92 R94 R94 R96 R96 R99 R99 R101 R101 R103 R103 R105 R105 R109 R109 R111 R111 R113 R113 R115 R115 R117 R117 R119 R119 R121 R121 R122 R122 R125 R125 R127 R127 R129 R129 R131 R131 R133 R133 R134 R134 R135 R135 R136 R136 R136 R136 R137 R137 R138 R138 R138 R139 R140 R140 R141 R141 R141 R141 R142 R143 R143 R143 R167 R167 R169 R169 R175 R175 R176 R176 R177 R177 R178 R178 R179 R179 R180 R180 R181 R181 R182 R182 R183 R183 R184 R184 R185 R185 R186 R186 R187 R187 R188 R188 R189 R189 R190 R190 R191 R191 R192 R192 R192 R192 R193 R193 R193 R197 R198 R199 R200 R204 R204 R205 R205 R207 R207 R208 R209 R210 R211 R217 R218 TP1 TP4 TP7 TP8 TP9 TP10 TP11 TP12 TP13 TP14 TP15 TP16 TP17 TP18 TP30 TP501 U4 Y3 Y4 Y5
